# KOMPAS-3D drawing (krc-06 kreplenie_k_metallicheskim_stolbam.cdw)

Views: Спереди 1, Проекционный вид 3, Вид 4
Referenced files: Крон.cdw
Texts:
  КРC-06
  Крепление к  металлическим столбам
  Никита
  Комплектность
  крепления к столбам
  Гайка М8
  Хомут
  Адаптер
  под любой   трубы
  любой размер
  Изготавливаем комплекты крепления к металлическим столбам
  (адаптеры крепления на столб) по стандартным чертежам, а также
  по вашим размерам.
  Покрытие: Порошковая покраска / Ц6хр / Горячее цинкование.
  POLYLINE_STYLE_0.18_RGB_0_0_0
  ООО "Центр инженерных
  услуг "МОДЕЛЬЕР"
  Крепление к
  металлическим столбам
Dimensions and other numbers on the sheet: 1:4; 2 шт.; 1 шт.; 100; 9; 30; 118; 138; 15; 5; 20; 40; 50; 6,5; 6 отв.; 45; 1:2; 2216.01.00.003-; 1; 0; 2; 3; 4; 6; 7; 8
